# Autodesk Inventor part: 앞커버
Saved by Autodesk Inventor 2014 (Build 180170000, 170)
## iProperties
Created: 2026-07
Part Number: 앞커버
Material: 일반
Document SubType Name: Modeling
Designer: dg
Density: 1 g/cm^3
Appearance: 기본값
Author: dg
Author: jhkim
Creation Date: 2026-07-02
Sending System: Autodesk Inventor 2027
Preprocessor: ST-DEVELOPER v20.1
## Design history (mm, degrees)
node "앞커버1"
node "솔리드1"
node "기준1"
